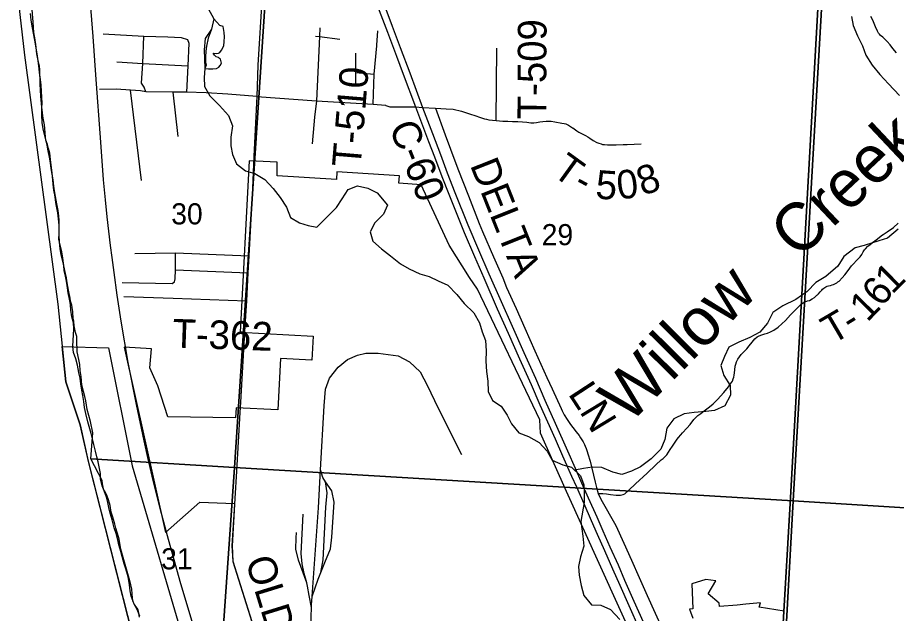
# Model space of a CAD drawing. Extents: x 0 to 45.4, y -2.2 to 22.
# Drawn here: x 3.357 to 5.099, y 16.002 to 17.183 of the extents above; entities that cross this region are included whole.
import ezdxf

# ---------------------------------------------------------------- set-up
doc = ezdxf.new("R2010")
doc.units = 0
for name, color, linetype in [('GM_X_Corporation', 7, 'Continuous'), ('GM_X_County_Road', 7, 'Continuous'), ('GM_X_County_Road_Text', 7, 'Continuous'), ('GM_X_Major_River', 7, 'Continuous'), ('GM_X_Minor_Lake', 7, 'Continuous'), ('GM_X_Minor_River', 7, 'Continuous'), ('GM_X_Minor_River_Text', 7, 'Continuous'), ('GM_X_Rail_Line', 7, 'Continuous'), ('GM_X_Section_Text', 7, 'Continuous'), ('GM_X_Township_Road', 7, 'Continuous'), ('GM_X_Township_Road_Text', 7, 'Continuous'), ('GM_X_US_Route', 7, 'Continuous')]:
    doc.layers.add(name, color=color, linetype=linetype)

msp = doc.modelspace()

# ---------------------------------------------------------------- linework, layer by layer
at = {"layer": 'GM_X_Corporation'}
for points in [[(3.854, 17.3067), (3.7867, 16.2913), (3.5022, 16.3086), (3.5064, 16.3597), (3.5014, 16.3821), (3.4954, 16.406), (3.4924, 16.423), (3.4905, 16.4317), (3.4875, 16.4416), (3.4848, 16.4541), (3.4833, 16.4715), (3.4814, 16.4833), (3.4803, 16.4954), (3.4784, 16.5052), (3.4754, 16.5204), (3.4754, 16.5257), (3.4747, 16.5382), (3.4743, 16.5507), (3.472, 16.559), (3.4694, 16.5723), (3.4686, 16.581), (3.4675, 16.5859), (3.4667, 16.6), (3.4649, 16.6128), (3.4622, 16.6208), (3.4611, 16.6269), (3.4584, 16.6424), (3.4547, 16.661), (3.4539, 16.667), (3.452, 16.6754), (3.4479, 16.6943), (3.4433, 16.7136), (3.4414, 16.7246), (3.4403, 16.7383), (3.4396, 16.7515), (3.4396, 16.7712), (3.4384, 16.7841), (3.4369, 16.7962), (3.4339, 16.8122), (3.4313, 16.8319), (3.4294, 16.8372), (3.4286, 16.8459), (3.426, 16.8751), (3.4234, 16.8955), (3.4211, 16.9145), (3.4185, 16.9232), (3.4166, 16.9315), (3.4135, 16.9398), (3.4128, 16.9463), (3.4109, 16.963), (3.4105, 16.9705), (3.4079, 16.9838), (3.4064, 16.9944), (3.4053, 17.0054), (3.4034, 17.027), (3.4019, 17.0516), (3.4011, 17.0793), (3.4004, 17.0869), (3.3981, 17.0982), (3.3955, 17.1115), (3.3936, 17.1297), (3.3913, 17.1429), (3.3894, 17.1536), (3.3879, 17.174), (3.3864, 17.1994)], [(3.3572, 17.2298), (3.3712, 17.1086), (3.4371, 16.6152), (3.4526, 16.4608), (3.481, 16.3756), (3.4973, 16.3038), (3.6446, 15.7252), (3.6802, 15.6336), (3.8978, 15.2272), (3.9542, 15.1285)], [(3.3572, 17.2298), (3.3712, 17.1086), (3.4371, 16.6152), (3.4526, 16.4608), (3.481, 16.3756), (3.4973, 16.3038), (3.6446, 15.7252), (3.6802, 15.6336), (3.8978, 15.2272), (3.9542, 15.1285)], [(4.9442, 17.2251), (4.9098, 16.6105), (4.8879, 16.2195), (4.8522, 15.6106), (4.8608, 15.5664), (4.8595, 15.5557), (4.858, 15.5432), (4.8578, 15.5386), (4.8566, 15.5019), (4.8525, 15.4406), (4.8498, 15.3908), (4.8494, 15.3832), (4.8455, 15.3119), (4.8407, 15.1929), (4.8223, 15.0904)], [(4.8223, 15.0904), (4.8407, 15.1929), (4.8455, 15.3119), (4.8494, 15.3832), (4.8498, 15.3908), (4.8525, 15.4406), (4.8566, 15.5019), (4.8578, 15.5386), (4.858, 15.5432), (4.8595, 15.5557), (4.8608, 15.5664), (4.8522, 15.6106), (4.8879, 16.2195), (4.9098, 16.6105), (4.9442, 17.2251)], [(4.5812, 15.9435), (4.4446, 16.2437), (4.3934, 16.3594), (4.3918, 16.3857), (4.2682, 16.6447), (4.2527, 16.6679), (4.2122, 16.7316), (4.1568, 16.8517), (4.1126, 16.8545), (4.1137, 16.8691), (3.99, 16.8775), (3.9889, 16.8624), (3.8713, 16.8696), (3.8718, 16.8965), (3.8164, 16.8988), (3.7983, 16.5593), (3.9429, 16.5516), (3.9403, 16.5042), (3.8782, 16.5073), (3.8727, 16.4054), (3.7903, 16.4095), (3.7893, 16.3895), (3.6548, 16.3915), (3.6352, 16.4528), (3.6192, 16.4889), (3.6223, 16.5265), (3.5686, 16.5294), (3.6504, 16.1624), (3.7183, 16.2225), (3.787, 16.2195), (3.7864, 16.2082), (3.7819, 16.1361), (3.7837, 16.1053), (3.8693, 15.8328)], [(3.5986, 15.9944), (3.597, 16.0058), (3.5963, 16.0088), (3.5948, 16.0119), (3.5918, 16.0156), (3.5891, 16.0198), (3.5868, 16.0236), (3.5857, 16.027), (3.5846, 16.0327), (3.5842, 16.041), (3.5838, 16.0498), (3.5819, 16.0585), (3.5781, 16.0714), (3.5706, 16.0986), (3.5664, 16.113), (3.5619, 16.129), (3.56, 16.1403), (3.5585, 16.149), (3.5555, 16.1604), (3.5517, 16.1706), (3.5502, 16.179), (3.5457, 16.1926), (3.5426, 16.2025), (3.5404, 16.2157), (3.5373, 16.2271), (3.5347, 16.2343), (3.5305, 16.2426), (3.5283, 16.2472), (3.5271, 16.2521), (3.5256, 16.2589), (3.5249, 16.2654), (3.5022, 16.3086), (3.7867, 16.2913), (3.7346, 15.5431)], [(4.8734, 15.9676), (4.8761, 16.0062), (4.8265, 16.0141), (4.8293, 16.0226), (4.8001, 16.02), (4.7829, 16.0185), (4.748, 16.0154), (4.7475, 16.022), (4.7256, 16.0404), (4.7407, 16.0666), (4.721, 16.0693), (4.6933, 16.0608), (4.695, 16.011), (4.6884, 16.0104), (4.6952, 15.9927)]]:
    msp.add_lwpolyline(points, dxfattribs=at)
for points in [[(4.9524, 17.2347), (4.8941, 16.2254), (3.7867, 16.2913), (3.854, 17.3067)], [(6.0488, 17.1677), (5.9818, 16.1569), (4.8941, 16.2254), (4.9524, 17.2347)], [(3.4456, 16.5311), (3.5376, 16.5285), (3.5844, 16.2943), (3.6943, 15.9191), (3.5982, 15.9075), (3.4983, 16.3007), (3.481, 16.3756), (3.4526, 16.4608)], [(3.7867, 16.2913), (4.8941, 16.2254), (4.837, 15.1953), (3.9034, 15.2421), (3.8921, 15.3073), (3.8792, 15.3304), (3.8675, 15.3551), (3.8622, 15.3661), (3.8531, 15.3846), (3.8425, 15.4055), (3.8335, 15.421), (3.8259, 15.4328), (3.8172, 15.446), (3.8077, 15.4604), (3.7986, 15.4786), (3.793, 15.4881), (3.7843, 15.5006), (3.7346, 15.5431)], [(4.8941, 16.2254), (5.9818, 16.1569), (5.9148, 15.1362), (4.837, 15.1953)]]:
    msp.add_lwpolyline(points, close=True, dxfattribs=at)
at = {"layer": 'GM_X_County_Road'}
for p, q in [((3.8107, 16.6214), (3.8077, 16.5712)), ((3.8077, 16.5712), (3.799, 16.4206)), ((3.799, 16.4206), (3.7979, 16.4005))]:
    msp.add_line(p, q, dxfattribs=at)
for points in [[(3.8421, 17.2281), (3.8334, 17.0889), (3.8311, 17.0268), (3.8255, 16.9085)], [(4.1853, 17.0035), (4.2043, 16.9509), (4.2147, 16.9219), (4.2294, 16.8834), (4.2506, 16.8294), (4.2721, 16.7749), (4.2785, 16.7592), (4.2999, 16.7089), (4.3184, 16.6669), (4.326, 16.6479), (4.3449, 16.6066), (4.3621, 16.5676), (4.3824, 16.5227), (4.4062, 16.4696), (4.4162, 16.4471), (4.434, 16.4082), (4.4361, 16.4034), (4.4403, 16.3954), (4.4463, 16.3861), (4.4513, 16.3783), (4.4547, 16.374), (4.46, 16.3671), (4.4636, 16.3627), (4.4674, 16.3579), (4.4702, 16.3543), (4.4727, 16.3501), (4.4754, 16.346), (4.4777, 16.3419), (4.4804, 16.3369), (4.4821, 16.3333), (4.4841, 16.329), (4.4861, 16.323), (4.4874, 16.3183), (4.4916, 16.3036), (4.502, 16.2618), (4.5044, 16.2515), (4.5079, 16.2394), (4.513, 16.2282), (4.5423, 16.1763), (4.5583, 16.1414), (4.5739, 16.1077), (4.5889, 16.0728), (4.6045, 16.0372), (4.6205, 16.0026), (4.6362, 15.9672)], [(3.8255, 16.9085), (3.8224, 16.8444), (3.8152, 16.7109), (3.8133, 16.6768), (3.8107, 16.6214)], [(3.7979, 16.4005), (3.7911, 16.284), (3.7878, 16.2299)], [(3.7878, 16.2299), (3.7821, 16.1356), (3.7839, 16.1048), (3.8669, 15.8405)]]:
    msp.add_lwpolyline(points, dxfattribs=at)
at = {"layer": 'GM_X_Major_River'}
for points in [[(3.3957, 17.1113), (3.3938, 17.1227), (3.3911, 17.1383), (3.3889, 17.1523), (3.387, 17.1626), (3.3844, 17.1781), (3.3825, 17.1914)], [(3.5997, 15.9966), (3.594, 16.0099), (3.5884, 16.0202), (3.5823, 16.0358), (3.5804, 16.0468), (3.5789, 16.0586), (3.5763, 16.0745), (3.5714, 16.0901), (3.5683, 16.1), (3.5642, 16.1148), (3.5615, 16.1247), (3.5581, 16.138), (3.5559, 16.1475), (3.5525, 16.1601), (3.5487, 16.1718), (3.5445, 16.1874), (3.5408, 16.2003), (3.5377, 16.2121), (3.5362, 16.222), (3.5332, 16.2323), (3.5287, 16.2452), (3.5245, 16.2547), (3.5215, 16.2684), (3.5215, 16.2794), (3.5196, 16.2893), (3.5166, 16.3026), (3.5143, 16.3121), (3.5113, 16.3235), (3.5083, 16.3368), (3.5056, 16.3478), (3.503, 16.3585), (3.4992, 16.3722), (3.4965, 16.382), (3.4924, 16.3984), (3.4901, 16.4102), (3.4882, 16.422), (3.4867, 16.4337), (3.4848, 16.4444), (3.4826, 16.4573), (3.481, 16.468), (3.4788, 16.4797), (3.4758, 16.4938), (3.4727, 16.5064), (3.4682, 16.5189), (3.4667, 16.5311), (3.4671, 16.5436), (3.4678, 16.5535), (3.4686, 16.5664), (3.4678, 16.5778), (3.4648, 16.59), (3.4629, 16.6033), (3.4618, 16.6143), (3.4599, 16.6246), (3.4576, 16.6375), (3.4561, 16.647), (3.4538, 16.6603), (3.452, 16.6702), (3.4497, 16.682), (3.4486, 16.6915), (3.447, 16.7059), (3.4448, 16.7184), (3.4421, 16.7302), (3.4391, 16.7431), (3.4395, 16.7564), (3.4399, 16.7659), (3.4395, 16.78), (3.4387, 16.7903), (3.4376, 16.8009), (3.4357, 16.8104), (3.4338, 16.8214), (3.4312, 16.8359), (3.4293, 16.8488), (3.4278, 16.8617), (3.4259, 16.8727), (3.4236, 16.8837), (3.4221, 16.8951), (3.4206, 16.9062), (3.418, 16.9187), (3.4157, 16.9301), (3.413, 16.9407), (3.4108, 16.9514), (3.4081, 16.9628), (3.4062, 16.9749), (3.4055, 16.9894), (3.4051, 17.0034), (3.4059, 17.0141), (3.4055, 17.0247), (3.4044, 17.0369), (3.404, 17.049), (3.4029, 17.06), (3.4006, 17.0741), (3.3991, 17.0874), (3.3976, 17.1018), (3.3957, 17.1113)]]:
    msp.add_lwpolyline(points, dxfattribs=at)
at = {"layer": 'GM_X_Minor_Lake'}
msp.add_line((3.7461, 17.1805), (3.7414, 17.16), dxfattribs=at)
for points in [[(3.766, 17.1268), (3.7668, 17.1359), (3.7672, 17.145), (3.7664, 17.1533), (3.7645, 17.1655), (3.7581, 17.1674), (3.7461, 17.1805)], [(3.7414, 17.16), (3.735, 17.1424), (3.7316, 17.1261), (3.7301, 17.1162), (3.7297, 17.1055), (3.7297, 17.0949), (3.7308, 17.0885), (3.7282, 17.0818), (3.7357, 17.0816), (3.7403, 17.0812), (3.7444, 17.0812), (3.7512, 17.0824), (3.7562, 17.085), (3.7588, 17.088), (3.7611, 17.0926), (3.7596, 17.1009), (3.7573, 17.1017), (3.7554, 17.1036), (3.7505, 17.1055), (3.7475, 17.1086), (3.7448, 17.1124), (3.7448, 17.1127), (3.7509, 17.112), (3.755, 17.1123), (3.7581, 17.1139), (3.7615, 17.1184), (3.766, 17.1268)]]:
    msp.add_lwpolyline(points, dxfattribs=at)
at = {"layer": 'GM_X_Minor_River'}
for points in [[(3.7348, 17.2011), (3.7461, 17.1805), (3.7414, 17.16), (3.7292, 17.1418), (3.7269, 17.119), (3.7276, 17.1008), (3.7282, 17.0818), (3.7267, 17.0643), (3.7273, 17.0461), (3.7379, 17.0278), (3.7575, 17.0087), (3.7748, 16.9889), (3.7831, 16.9683), (3.7799, 16.9463), (3.7799, 16.9288), (3.7828, 16.9113), (3.7911, 16.893), (3.8085, 16.8792), (3.8274, 16.8739), (3.847, 16.8624), (3.8636, 16.8441), (3.8772, 16.8265), (3.89, 16.8075), (3.8982, 16.7869), (3.9156, 16.7762), (3.933, 16.7708), (3.9504, 16.7677), (3.9892, 16.8063), (4.0006, 16.8238), (4.012, 16.842), (4.031, 16.8495), (4.0514, 16.8449), (4.0696, 16.8357), (4.0899, 16.8113), (4.0823, 16.7931), (4.0648, 16.7764), (4.0556, 16.7582), (4.0608, 16.7399), (4.0782, 16.7246), (4.0963, 16.7109), (4.116, 16.6948), (4.1333, 16.6849), (4.1545, 16.6749), (4.1726, 16.6695), (4.1908, 16.6611), (4.2097, 16.6527), (4.2278, 16.6343), (4.2421, 16.616), (4.261, 16.5977), (4.2723, 16.5779), (4.2775, 16.5604), (4.2842, 16.5429), (4.2857, 16.5223)], [(5.0094, 17.1849), (5.0131, 17.1674), (5.0213, 17.1468), (5.0311, 17.127), (5.0379, 17.1088), (5.0506, 17.089), (5.0657, 17.0699), (5.0831, 17.0516), (5.1049, 17.0287)], [(5.1023, 16.7635), (5.0811, 16.746), (5.0636, 16.7408), (5.0348, 16.731), (5.0166, 16.7265), (4.9946, 16.7091), (4.9824, 16.6901), (4.9588, 16.6697), (4.9391, 16.6576), (4.9216, 16.6402), (4.8996, 16.6243), (4.8737, 16.6115), (4.854, 16.5986), (4.8433, 16.5774), (4.8281, 16.5592), (4.8084, 16.5486), (4.7864, 16.5395), (4.7666, 16.5297), (4.7582, 16.5115), (4.7506, 16.4933), (4.7566, 16.4735), (4.7693, 16.4537), (4.77, 16.4347), (4.7586, 16.4134), (4.7381, 16.4044), (4.7207, 16.4022), (4.6979, 16.4), (4.6782, 16.3977), (4.6577, 16.3879), (4.644, 16.369), (4.6394, 16.3469), (4.6317, 16.3272), (4.6127, 16.3082), (4.5915, 16.2924), (4.574, 16.284), (4.5543, 16.2773), (4.5369, 16.2819), (4.515, 16.2911), (4.496, 16.2919), (4.4786, 16.2889), (4.4615, 16.2856)], [(4.2857, 16.5223), (4.2848, 16.5018), (4.2863, 16.4813), (4.2892, 16.4622), (4.2899, 16.4417), (4.2981, 16.4242), (4.3155, 16.4127), (4.3276, 16.3952), (4.3358, 16.3777), (4.3501, 16.3601), (4.3698, 16.3524), (4.391, 16.341), (4.4068, 16.3234), (4.4166, 16.3059), (4.4377, 16.2967), (4.4551, 16.2921), (4.4725, 16.2745), (4.4792, 16.257), (4.4799, 16.2395), (4.4798, 16.222), (4.4736, 16.184), (4.4773, 16.1551), (4.4795, 16.1353), (4.4726, 16.1141), (4.4687, 16.0951), (4.4702, 16.0776), (4.4739, 16.057), (4.4791, 16.0372), (4.4942, 16.0189), (4.5131, 16.0181), (4.532, 16.0097), (4.5508, 15.9899)]]:
    msp.add_lwpolyline(points, dxfattribs=at)
at = {"layer": 'GM_X_Rail_Line'}
for points in [[(3.7093, 15.9658), (3.6808, 16.0605), (3.656, 16.1481), (3.6403, 16.2075), (3.6238, 16.2743), (3.6152, 16.3113), (3.6078, 16.3441), (3.5926, 16.4159), (3.5766, 16.4991), (3.5626, 16.5814), (3.5548, 16.6331), (3.5486, 16.6776), (3.5447, 16.7076), (3.5416, 16.7314), (3.535, 16.7881), (3.5315, 16.8215), (3.5277, 16.8613), (3.5219, 16.9362), (3.512, 17.0696), (3.5067, 17.1453), (3.5018, 17.2117)], [(3.9576, 16.2864), (3.9648, 16.4137), (3.9673, 16.4466), (3.9751, 16.468), (3.9923, 16.4902), (4.0112, 16.5054), (4.0306, 16.514), (4.047, 16.5181), (4.0717, 16.5181), (4.1115, 16.5128), (4.1337, 16.5004), (4.1547, 16.4811), (4.1695, 16.4528), (4.19, 16.41), (4.2369, 16.3171)], [(3.9409, 16.0354), (3.9533, 16.2115), (3.9576, 16.2864)], [(3.9673, 16.2629), (3.9623, 16.2715), (3.9576, 16.2864)], [(3.9581, 16.0828), (3.9628, 16.1079), (3.9677, 16.2127), (3.9706, 16.2407), (3.9673, 16.2629)], [(3.9581, 16.0828), (3.966, 16.1026), (3.9771, 16.1301), (3.9796, 16.1531), (3.9845, 16.2226), (3.98, 16.2448), (3.9673, 16.2629)], [(3.9302, 16.0626), (3.9253, 16.0812), (3.9212, 16.1001), (3.9188, 16.1207), (3.9233, 16.1988)], [(3.9302, 16.0626), (3.9138, 16.1075), (3.9085, 16.1293), (3.9089, 16.1515), (3.9101, 16.1622)], [(3.9409, 16.0354), (3.9529, 16.0697), (3.9581, 16.0828)], [(3.9395, 16.0134), (3.9352, 16.0376), (3.9319, 16.0557), (3.9302, 16.0626)], [(3.9395, 16.0134), (3.9397, 16.0191), (3.9409, 16.0354)], [(3.9784, 15.7783), (3.9664, 15.8005), (3.9422, 15.8371), (3.9348, 15.8588), (3.9323, 15.879), (3.9332, 15.8975), (3.9381, 15.9768), (3.9395, 16.0134)]]:
    msp.add_lwpolyline(points, dxfattribs=at)
at = {"layer": 'GM_X_Township_Road'}
for p, q in [((4.3056, 16.9792), (4.307, 17.1221)), ((4.0269, 17.0739), (4.0639, 17.0706)), ((3.6027, 16.8598), (3.5811, 17.0389)), ((3.6651, 17.0352), (3.675, 16.9472)), ((4.1853, 17.0035), (4.2064, 17.0021)), ((3.6703, 16.6827), (3.8133, 16.6768)), ((3.5678, 16.6302), (3.6654, 16.6266)), ((3.6654, 16.6266), (3.8107, 16.6214))]:
    msp.add_line(p, q, dxfattribs=at)
for points in [[(5.0989, 17.1131), (5.0914, 17.1218), (5.0861, 17.1288), (5.0803, 17.1356), (5.0768, 17.139), (5.0715, 17.1444), (5.0673, 17.1478), (5.0653, 17.1502), (5.0634, 17.1523), (5.0611, 17.1563), (5.0569, 17.1649), (5.0519, 17.1778), (5.0482, 17.1853)], [(3.9563, 17.1626), (3.9555, 17.1453), (3.9492, 17.0182), (3.9458, 16.9855)], [(4.069, 17.1272), (4.0691, 17.1281), (4.071, 17.1567)], [(3.5268, 17.1507), (3.6075, 17.1465), (3.6546, 17.1447), (3.6814, 17.1433), (3.6939, 17.1394)], [(3.611, 17.0361), (3.6081, 17.0448), (3.6027, 17.0532), (3.6054, 17.0917), (3.6075, 17.1465)], [(3.6939, 17.1394), (3.6966, 17.1322), (3.6945, 17.0872), (3.6922, 17.0352)], [(3.9472, 17.1464), (3.9555, 17.1453), (3.9958, 17.14)], [(4.062, 17.0112), (4.0639, 17.0706), (4.069, 17.1272)], [(4.0269, 17.1122), (4.0269, 17.0739), (4.0269, 17.0531)], [(3.5538, 17.0952), (3.6054, 17.0917), (3.6945, 17.0872)], [(3.8311, 17.0268), (3.7735, 17.0314), (3.731, 17.0342), (3.6922, 17.0352), (3.6651, 17.0352), (3.611, 17.0361), (3.6006, 17.0379), (3.5811, 17.0389), (3.5523, 17.0411), (3.5198, 17.0406)], [(3.8311, 17.0268), (3.9492, 17.0182), (4.062, 17.0112), (4.0859, 17.0091), (4.0869, 17.0088)], [(4.0869, 17.0088), (4.0946, 17.0062), (4.1162, 17.0061)], [(4.1162, 17.0061), (4.1458, 17.0059), (4.1596, 17.0047), (4.1853, 17.0035)], [(4.2064, 17.0021), (4.2203, 17.0012), (4.2369, 16.9975), (4.2565, 16.9912), (4.2613, 16.9898), (4.2762, 16.9845), (4.2827, 16.9825), (4.2864, 16.9815), (4.2913, 16.9805), (4.2984, 16.9799)], [(3.9458, 16.9855), (3.9443, 16.9704), (3.9412, 16.9327)], [(4.2984, 16.9799), (4.3056, 16.9792), (4.3184, 16.9778), (4.3287, 16.9775), (4.3381, 16.9773), (4.3482, 16.9768), (4.3578, 16.9766), (4.3666, 16.9756), (4.3739, 16.9747), (4.3803, 16.9743), (4.3854, 16.9749), (4.3921, 16.9764), (4.3979, 16.977), (4.4046, 16.9776), (4.4087, 16.9778), (4.4142, 16.9774), (4.4218, 16.9763), (4.4354, 16.974), (4.4401, 16.9733), (4.4435, 16.9724), (4.4461, 16.9714), (4.4491, 16.9697), (4.457, 16.9646), (4.4576, 16.9642), (4.4598, 16.9622), (4.4651, 16.9587), (4.4693, 16.9562), (4.4756, 16.9526), (4.4826, 16.9496), (4.4869, 16.9468), (4.4913, 16.944), (4.498, 16.9397), (4.5049, 16.9357), (4.5087, 16.9343), (4.5133, 16.9325), (4.5165, 16.9316), (4.52, 16.9313), (4.5263, 16.9311), (4.543, 16.9307), (4.557, 16.9312), (4.5652, 16.9313), (4.5929, 16.9325)], [(4.9079, 16.6129), (4.91, 16.6149), (4.9138, 16.6173), (4.9179, 16.6196), (4.9227, 16.6214), (4.9265, 16.622), (4.9317, 16.6252), (4.9362, 16.6282), (4.9411, 16.6327), (4.9424, 16.6336), (4.9442, 16.6355), (4.9473, 16.6391), (4.9505, 16.6425), (4.9524, 16.6446), (4.9546, 16.6464), (4.9567, 16.6477), (4.959, 16.6491), (4.9617, 16.6503), (4.9643, 16.6513), (4.9679, 16.6521), (4.9714, 16.653), (4.974, 16.6541), (4.9765, 16.6551), (4.9803, 16.6572), (4.9826, 16.6589), (4.9852, 16.6608), (4.9911, 16.6669), (4.9962, 16.673), (5.0031, 16.6815), (5.0094, 16.6906), (5.0236, 16.7052), (5.0267, 16.709), (5.0299, 16.7135), (5.0329, 16.7184), (5.0355, 16.7225), (5.0374, 16.7249), (5.0421, 16.7297), (5.0456, 16.7326), (5.0511, 16.7369), (5.0586, 16.7427), (5.0708, 16.7521), (5.0712, 16.7525), (5.0721, 16.7532), (5.0806, 16.7583), (5.0929, 16.7668), (5.102, 16.7752)], [(3.5642, 16.6582), (3.6635, 16.6558), (3.668, 16.659), (3.6696, 16.6652), (3.6703, 16.6827), (3.6699, 16.7167)], [(3.5892, 16.7151), (3.6699, 16.7167), (3.8152, 16.7109)], [(4.5079, 16.2394), (4.5171, 16.2395), (4.5241, 16.2389), (4.5319, 16.2377), (4.5431, 16.2364), (4.5516, 16.2361), (4.5572, 16.2375), (4.5604, 16.2389), (4.5686, 16.2459), (4.5817, 16.2585), (4.6049, 16.2797), (4.6221, 16.2962), (4.6324, 16.3064), (4.6362, 16.3091), (4.639, 16.3116), (4.6434, 16.316), (4.6506, 16.3268), (4.6547, 16.3334), (4.6601, 16.3417), (4.6643, 16.3472), (4.6668, 16.3503), (4.6711, 16.3556), (4.6747, 16.3596), (4.683, 16.3689), (4.6899, 16.3767), (4.6971, 16.386), (4.7008, 16.3898), (4.7053, 16.3945), (4.7112, 16.3982), (4.7174, 16.4038), (4.7282, 16.4114), (4.7284, 16.4116), (4.7356, 16.4174), (4.7439, 16.4261), (4.7568, 16.4399), (4.766, 16.4509), (4.77, 16.4569), (4.7736, 16.4622), (4.7754, 16.4666), (4.7765, 16.4704), (4.7771, 16.4741), (4.7778, 16.479), (4.7785, 16.485), (4.7794, 16.4918), (4.7802, 16.4959), (4.7818, 16.5004), (4.7842, 16.5058), (4.7874, 16.5106), (4.7909, 16.5151), (4.7967, 16.5208), (4.8025, 16.5267), (4.807, 16.5321), (4.8125, 16.5394), (4.8181, 16.5462), (4.8227, 16.5499), (4.8268, 16.5521), (4.8317, 16.5542), (4.838, 16.5561), (4.843, 16.5576), (4.8493, 16.56), (4.8558, 16.5632), (4.8644, 16.5693), (4.8788, 16.5825), (4.8885, 16.5936), (4.8962, 16.6009), (4.903, 16.6082), (4.9079, 16.6129)]]:
    msp.add_lwpolyline(points, dxfattribs=at)
at = {"layer": 'GM_X_US_Route'}
for points in [[(4.0707, 17.2055), (4.0902, 17.154), (4.1083, 17.1063), (4.1213, 17.0707), (4.1458, 17.0059), (4.1714, 16.9377), (4.1832, 16.9069), (4.1978, 16.8678), (4.2118, 16.833), (4.2421, 16.7572), (4.2624, 16.7091), (4.2809, 16.667), (4.3078, 16.6058), (4.3294, 16.5573), (4.3515, 16.5069), (4.3747, 16.4556), (4.3921, 16.4156), (4.4225, 16.3478), (4.437, 16.3145), (4.455, 16.2739), (4.4645, 16.253), (4.4789, 16.2196), (4.4939, 16.186), (4.5056, 16.159), (4.5201, 16.1266), (4.5361, 16.0903), (4.5506, 16.0578), (4.5684, 16.0175), (4.5886, 15.9714)], [(4.0849, 17.2051), (4.0994, 17.1661), (4.1156, 17.1236), (4.1343, 17.0734), (4.1596, 17.0047), (4.1792, 16.953), (4.1952, 16.9119), (4.2085, 16.8755), (4.2238, 16.8362), (4.2496, 16.7724), (4.2705, 16.7227), (4.2911, 16.675), (4.3152, 16.6202), (4.337, 16.5715), (4.3602, 16.5194), (4.3832, 16.468), (4.4021, 16.4248), (4.4225, 16.3791), (4.4468, 16.3241), (4.4621, 16.2897), (4.4745, 16.2608), (4.4878, 16.2307), (4.5047, 16.1933), (4.5169, 16.1654), (4.5309, 16.1338), (4.547, 16.0983), (4.56, 16.0677), (4.5786, 16.0265), (4.5967, 15.9854)]]:
    msp.add_lwpolyline(points, dxfattribs=at)

# ---------------------------------------------------------------- texts
at = {"layer": 'GM_X_County_Road_Text'}
for s, height, rotation, p in [('C-60', 0.05682, 291.8015, (4.0925, 16.966)), ('DELTA', 0.05682, 291.685, (4.2531, 16.8908)), ('L', 0.0568, 303.1568, (4.4469, 16.4372)), ('N', 0.0568, 301.3202, (4.4698, 16.4021)), ('OLD US52', 0.05682, 287.2024, (3.8081, 16.1067))]:
    msp.add_text(s, height=height, rotation=rotation, dxfattribs=at).set_placement(p)
at = {"layer": 'GM_X_Minor_River_Text'}
for s, height, rotation, p in [('Creek', 0.09474, 43.2807, (4.9045, 16.702)), ('Willow', 0.09475, 45.243, (4.5687, 16.375))]:
    msp.add_text(s, height=height, rotation=rotation, dxfattribs=at).set_placement(p)
at = {"layer": 'GM_X_Section_Text'}
for s, p in [('30', (3.6617, 16.7731)), ('29', (4.3958, 16.7318)), ('31', (3.6417, 16.0893))]:
    msp.add_text(s, height=0.04186, rotation=0, dxfattribs=at).set_placement(p)
at = {"layer": 'GM_X_Township_Road_Text'}
for s, height, rotation, p in [('T-509', 0.05682, 89.7193, (4.4045, 16.9813)), ('T-510', 0.05682, 85.2833, (4.0367, 16.8851)), ('T', 0.0568, 324.1291, (4.4144, 16.8721)), ('8', 0.0568, 19.4314, (4.5959, 16.8293)), ('5', 0.0568, 355.928, (4.5012, 16.8245)), ('0', 0.0568, 6.5317, (4.5476, 16.8222)), ('-', 0.0568, 331.6167, (4.4556, 16.8429)), ('1', 0.0568, 44.7226, (5.0902, 16.6331)), ('6', 0.0568, 50.8232, (5.0692, 16.6071)), ('1', 0.0568, 45.5093, (5.0408, 16.5779)), ('T', 0.0568, 30.3684, (4.9714, 16.5341)), ('T-362', 0.05682, 358.0347, (3.6633, 16.5291)), ('-', 0.0568, 31.626, (5.0092, 16.5563))]:
    msp.add_text(s, height=height, rotation=rotation, dxfattribs=at).set_placement(p)

doc.saveas('drawing.dxf')
